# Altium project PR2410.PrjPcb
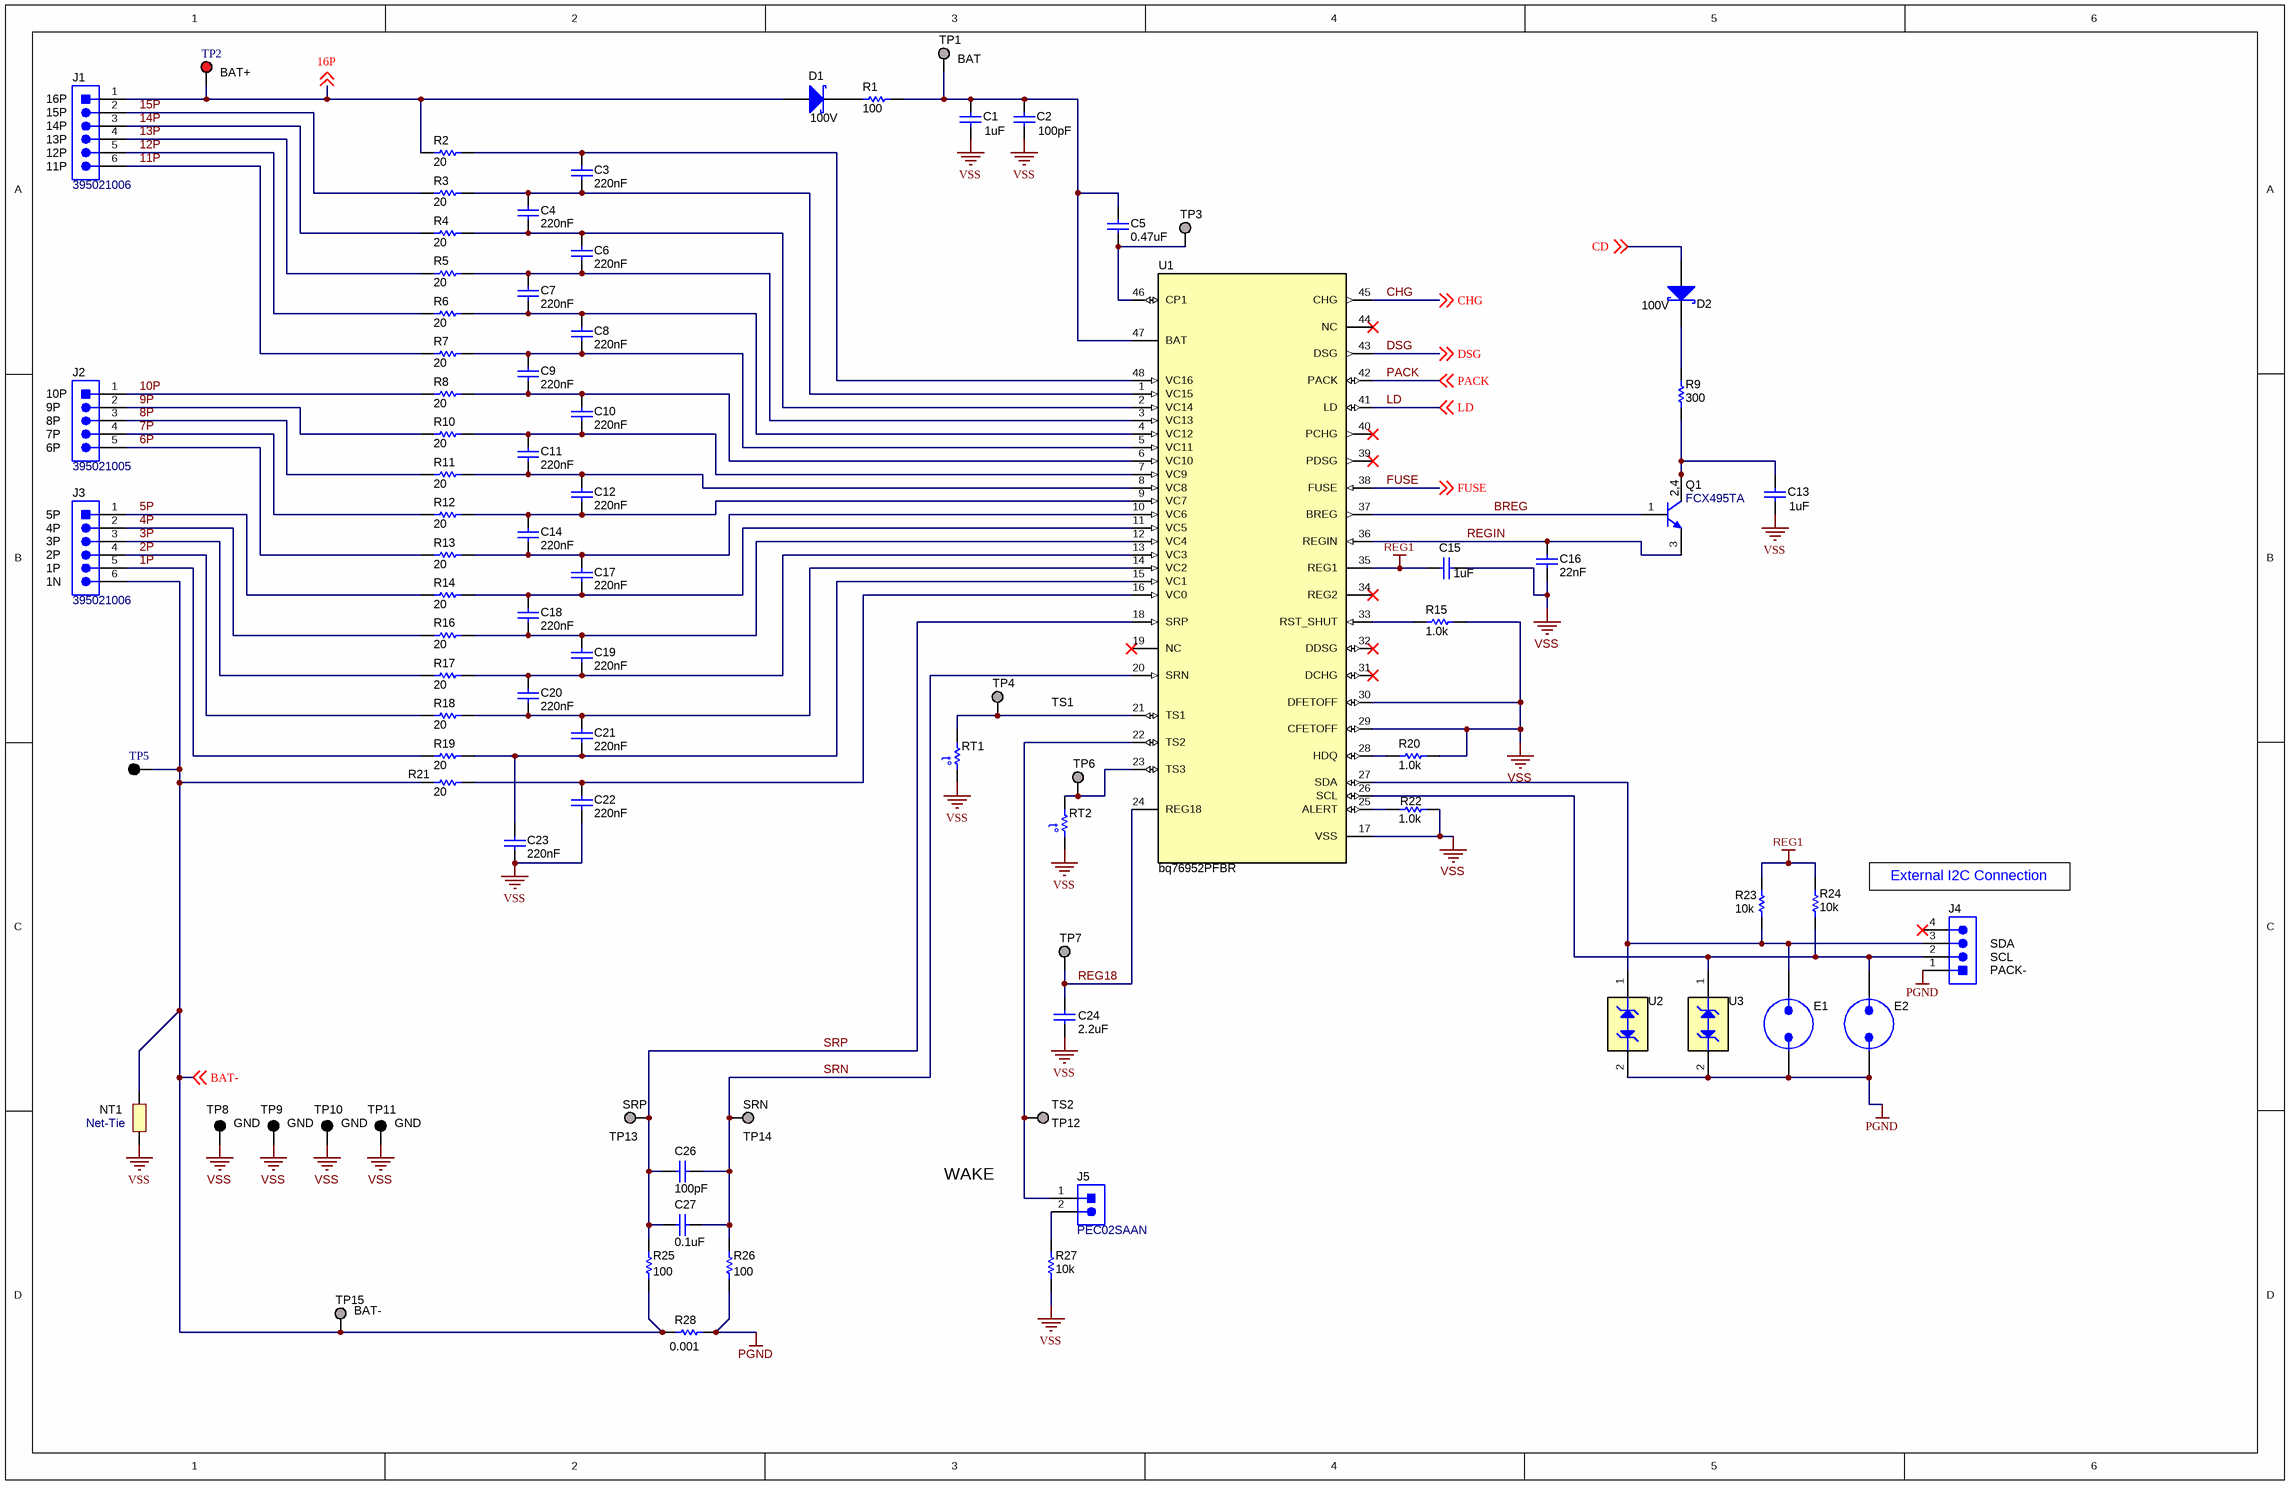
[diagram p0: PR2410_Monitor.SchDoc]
PCB_Rev: A; PRJ_Customer: Public Release; PRJ_Number: PR2410; PRJ_Title: BQ76952 2-layer test board; SCH_Rev: A; TID: N/A
3 sheets, 144 parts. Net scope: global (net labels, ports and power ports of the same name join across sheets).
Board file: PR2410.PcbDoc
Sheets:
  PR2410_Monitor.SchDoc
  PR2410_FETs.SchDoc
  PR2410_Hardware.SchDoc

## Sheet PR2410_Monitor.SchDoc: Monitor
size 431 x 279 mm; Date: Not shown in title block; ApprovedBy: Not shown in title block; CheckedBy: Not shown in title block; Author: Not shown in title block; CompanyName: Not shown in title block; Engineer: Not shown in title block; Organization: Not shown in title block; Address1: Not shown in title block; Address2: Not shown in title block; Address3: Not shown in title block; Address4: Not shown in title block; DocumentNumber: 1; Revision: Use project parameter SCH_Rev; SheetNumber: 1; SheetTotal: 3; PageSetup: Record=PageOptions¦CenterHorizontal=True¦CenterVertical=True¦PrintScale=1.00¦XCorrection=1.00¦YCorrection=1.00¦PrintKind=0¦BorderSize=5000000¦LeftOffset=0¦BottomOffset=0¦Orientation=2¦PaperLength=1000¦PaperWidth=1000¦Scale=100¦PaperSource=15¦PrintQuality=600¦MediaType=1¦DitherType=10¦PaperKind=Letter¦PrintScaleMode=1

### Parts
C1  ValueDisplayed: 1uF  [1206_180L]  (hidden comment: C3216X7R2A105K160AA)
C2  ValueDisplayed: 100pF  [0603]  (hidden comment: GCM1885C2A101JA16D)
C3  Cap_F: 220nF  [0603S]  (hidden comment: C1608X7R1H224K080AB)
C4  Cap_F: 220nF  [0603S]  (hidden comment: C1608X7R1H224K080AB)
C5  ValueDisplayed: 0.47uF  [0805_HV]  (hidden comment: GCM219R71E474KA55D)
C6  Cap_F: 220nF  [0603S]  (hidden comment: C1608X7R1H224K080AB)
C7  Cap_F: 220nF  [0603S]  (hidden comment: C1608X7R1H224K080AB)
C8  Cap_F: 220nF  [0603S]  (hidden comment: C1608X7R1H224K080AB)
C9  Cap_F: 220nF  [0603S]  (hidden comment: C1608X7R1H224K080AB)
C10  Cap_F: 220nF  [0603S]  (hidden comment: C1608X7R1H224K080AB)
C11  Cap_F: 220nF  [0603S]  (hidden comment: C1608X7R1H224K080AB)
C12  Cap_F: 220nF  [0603S]  (hidden comment: C1608X7R1H224K080AB)
C13  ValueDisplayed: 1uF  [1206_180]  (hidden comment: C3216X7R2A105K160AA)
C14  Cap_F: 220nF  [0603S]  (hidden comment: C1608X7R1H224K080AB)
C15  ValueDisplayed: 1uF  [0805_HV]  (hidden comment: EMK212B7105KG-T)
C16  Cap_F: 22nF  [0603]  (hidden comment: C0603C223K4RACTU)
C17  Cap_F: 220nF  [0603S]  (hidden comment: C1608X7R1H224K080AB)
C18  Cap_F: 220nF  [0603S]  (hidden comment: C1608X7R1H224K080AB)
C19  Cap_F: 220nF  [0603S]  (hidden comment: C1608X7R1H224K080AB)
C20  Cap_F: 220nF  [0603S]  (hidden comment: C1608X7R1H224K080AB)
C21  Cap_F: 220nF  [0603S]  (hidden comment: C1608X7R1H224K080AB)
C22  Cap_F: 220nF  [0603S]  (hidden comment: C1608X7R1H224K080AB)
C23  Cap_F: 220nF  [0603S]  (hidden comment: C1608X7R1H224K080AB)
C24  ValueDisplayed: 2.2uF  [0805_HV]  (hidden comment: EMK212B7225KG-T)
C26  ValueDisplayed: 100pF  [0603]  (hidden comment: GCM1885C2A101JA16D)
C27  ValueDisplayed: 0.1uF  [0603]  (hidden comment: 885012206095)
D1  value 100V  [SOD-123]  (hidden comment: BAT46W-7-F)
D2  value 100V  [SOD-123]  (hidden comment: BAT46W-7-F)
E1  Spark Gap  [SPARK_GAP2]  (value not drawn)  (no BOM)
E2  Spark Gap  [SPARK_GAP2]  (value not drawn)  (no BOM)
J1  395021006  [HEADER_395021006]
J2  395021005  [HEADER_395021005]
J3  395021006  [HEADER_395021006]
J4  22/05/3041  [CONN_22-05-3041]  (value not drawn)
J5  PEC02SAAN  [CONN_PEC02SAAN]
NT1  Net-Tie  [Net-Tie_10milWide_30milLong]  (net tie, no BOM)
Q1  FCX495TA  [SOT-89-3]
R1  ValueDisplayed: 100  [1210]  (hidden comment: CRCW1210100RFKEA)
R2  ValueDisplayed: 20  [1210]  (hidden comment: ERJ-14YJ200U)
R3  ValueDisplayed: 20  [1210]  (hidden comment: ERJ-14YJ200U)
R4  ValueDisplayed: 20  [1210]  (hidden comment: ERJ-14YJ200U)
R5  ValueDisplayed: 20  [1210]  (hidden comment: ERJ-14YJ200U)
R6  ValueDisplayed: 20  [1210]  (hidden comment: ERJ-14YJ200U)
R7  ValueDisplayed: 20  [1210]  (hidden comment: ERJ-14YJ200U)
R8  ValueDisplayed: 20  [1210]  (hidden comment: ERJ-14YJ200U)
R9  ValueDisplayed: 300  [2512]  (hidden comment: CRCW2512300RJNEG)
R10  ValueDisplayed: 20  [1210]  (hidden comment: ERJ-14YJ200U)
R11  ValueDisplayed: 20  [1210]  (hidden comment: ERJ-14YJ200U)
R12  ValueDisplayed: 20  [1210]  (hidden comment: ERJ-14YJ200U)
R13  ValueDisplayed: 20  [1210]  (hidden comment: ERJ-14YJ200U)
R14  ValueDisplayed: 20  [1210]  (hidden comment: ERJ-14YJ200U)
R15  ValueDisplayed: 1.0k  [0603]  (hidden comment: CRCW06031K00JNEA)
R16  ValueDisplayed: 20  [1210]  (hidden comment: ERJ-14YJ200U)
R17  ValueDisplayed: 20  [1210]  (hidden comment: ERJ-14YJ200U)
R18  ValueDisplayed: 20  [1210]  (hidden comment: ERJ-14YJ200U)
R19  ValueDisplayed: 20  [1210]  (hidden comment: ERJ-14YJ200U)
R20  ValueDisplayed: 1.0k  [0603]  (hidden comment: CRCW06031K00JNEA)
R21  ValueDisplayed: 20  [1210]  (hidden comment: ERJ-14YJ200U)
R22  ValueDisplayed: 1.0k  [0603]  (hidden comment: CRCW06031K00JNEA)
R23  ValueDisplayed: 10k  [0603]  (hidden comment: CRCW060310K0JNEA)
R24  ValueDisplayed: 10k  [0603]  (hidden comment: CRCW060310K0JNEA)
R25  ValueDisplayed: 100  [0603]  (hidden comment: Resistor)
R26  ValueDisplayed: 100  [0603]  (hidden comment: Resistor)
R27  ValueDisplayed: 10k  [0603]  (hidden comment: CRCW060310K0JNEA)
R28  ValueDisplayed: 0.001  [1210M]  (hidden comment: Resistor)
RT1  Thermistor  [THERMISTOR_103AT-2]  (value not drawn)
RT2  Thermistor  [THERMISTOR_103AT-2]  (value not drawn)
TP1  TESTPOINT  [TP_VIA_060RND040]  (value not drawn)  (no BOM)
TP2  TESTPOINT  [Keystone5010]  (value not drawn)
TP3  TESTPOINT  [TP_VIA_060RND040]  (value not drawn)  (no BOM)
TP4  TESTPOINT  [TP_VIA_060RND040]  (value not drawn)  (no BOM)
TP5  TESTPOINT  [Keystone5011]  (value not drawn)
TP6  TESTPOINT  [TP_VIA_060RND040]  (value not drawn)  (no BOM)
TP7  TESTPOINT  [TP_VIA_060RND040]  (value not drawn)  (no BOM)
TP8  5006  [Keystone5006]  (value not drawn)
TP9  5006  [Keystone5006]  (value not drawn)
TP10  5006  [Keystone5006]  (value not drawn)
TP11  5006  [Keystone5006]  (value not drawn)
TP12  TESTPOINT  [TP_VIA_060RND040]  (value not drawn)  (no BOM)
TP13  TESTPOINT  [TP_VIA_060RND040]  (value not drawn)  (no BOM)
TP14  TESTPOINT  [TP_VIA_060RND040]  (value not drawn)  (no BOM)
TP15  TESTPOINT  [TP_VIA_060RND040]  (value not drawn)  (no BOM)
U1  bq76952PFBR  [PFB0048A_N]
U2  TPD1E10B06DPYR  [DPY0002A]  (value not drawn)
U3  TPD1E10B06DPYR  [DPY0002A]  (value not drawn)

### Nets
PGND: E1.2 E2.2 J4.1 R26.1 R28.1 U2.2(A) U3.2(A)
REG1: C15.2 R23.1 R24.1 U1.35(REG1)
VSS: C1.2 C2.2 C13.2 C15.1 C16.1 C22.2 C23.2 C24.1 NT1.1 R15.1 R20.1 R22.1 R27.1 RT1.2 RT2.2 TP8.1 TP9.1 TP10.1 TP11.1 U1.17(VSS) U1.29(CFETOFF) U1.30(DFETOFF)
1P: J3.5 R19.1
2P: J3.4 R18.1
3P: J3.3 R17.1
4P: J3.2 R16.1
5P: J3.1 R14.1
6P: J2.5 R13.1
7P: J2.4 R12.1
8P: J2.3 R11.1
9P: J2.2 R10.1
10P: J2.1 R8.1
11P: J1.6 R7.1
12P: J1.5 R6.1
13P: J1.4 R5.1
14P: J1.3 R4.1
15P: J1.2 R3.1
16P: D1.2(A) J1.1 R2.1 TP2.1 ; off-sheet 16P
BAT-: J3.6 NT1.2 R21.1 R25.1 R28.2 TP5.1 TP15.1 ; off-sheet BAT-
BREG: Q1.1(B) U1.37(BREG)
CD: D2.2(A) ; off-sheet CD
CHG: U1.45(CHG) ; off-sheet CHG
DSG: U1.43(DSG) ; off-sheet DSG
FUSE: U1.38(FUSE) ; off-sheet FUSE
LD: U1.41(LD) ; off-sheet LD
PACK: U1.42(PACK) ; off-sheet PACK
REG18: C24.2 TP7.1 U1.24(REG18)
REGIN: C16.2 Q1.3(E) U1.36(REGIN)
SRN: C26.2 C27.2 R26.2 TP14.1 U1.20(SRN)
SRP: C26.1 C27.1 R25.2 TP13.1 U1.18(SRP)
NetC1_1: C1.1 C2.1 C5.1 R1.1 TP1.1 U1.47(BAT)
NetC3_1: C3.1 R2.2 U1.48(VC16)
NetC3_2: C3.2 C4.1 R3.2 U1.1(VC15)
NetC4_2: C4.2 C6.1 R4.2 U1.2(VC14)
NetC5_2: C5.2 TP3.1 U1.46(CP1)
NetC6_2: C6.2 C7.1 R5.2 U1.3(VC13)
NetC7_2: C7.2 C8.1 R6.2 U1.4(VC12)
NetC8_2: C8.2 C9.1 R7.2 U1.5(VC11)
NetC9_2: C9.2 C10.1 R8.2 U1.6(VC10)
NetC10_2: C10.2 C11.1 R10.2 U1.7(VC9)
NetC11_2: C11.2 C12.1 R11.2 U1.8(VC8)
NetC12_2: C12.2 C14.1 R12.2 U1.9(VC7)
NetC13_1: C13.1 Q1.2(C) Q1.4(C) R9.1
NetC14_2: C14.2 C17.1 R13.2 U1.10(VC6)
NetC17_2: C17.2 C18.1 R14.2 U1.11(VC5)
NetC18_2: C18.2 C19.1 R16.2 U1.12(VC4)
NetC19_2: C19.2 C20.1 R17.2 U1.13(VC3)
NetC20_2: C20.2 C21.1 R18.2 U1.14(VC2)
NetC21_2: C21.2 C23.1 R19.2 U1.15(VC1)
NetC22_1: C22.1 R21.2 U1.16(VC0)
NetD1_1: D1.1(K) R1.2
NetD2_1: D2.1(K) R9.2
NetE1_1: E1.1 J4.3 R23.2 U1.27(SDA) U2.1(K)
NetE2_1: E2.1 J4.2 R24.2 U1.26(SCL) U3.1(K)
NetJ5_1: J5.1 TP12.1 U1.22(TS2)
NetJ5_2: J5.2 R27.2
NetR15_2: R15.2 U1.33(RST_SHUT)
NetR20_2: R20.2 U1.28(HDQ)
NetR22_2: R22.2 U1.25(ALERT)
NetRT1_1: RT1.1 TP4.1 U1.21(TS1)
NetRT2_1: RT2.1 TP6.1 U1.23(TS3)

Not connected (* = marked no-connect by the designer): J4 4*; U1 19(NC)* 31(DCHG)* 32(DDSG)* 34(REG2)* 39(PDSG)* 40(PCHG)* 44(NC)*

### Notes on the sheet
- (near J1) 16P
- (near TP2) BAT+
- (near TP1) BAT
- (near J1) 12P
- (near J1) 11P
- (near J1) 14P
- (near J1) 13P
- (near J1) 15P
- (near J2) 7P
- (near J2) 8P
- (near J2) 9P
- (near J2) 10P
- (near J2) 6P
- (near J3) 2P
- (near J3) 1P
- (near J3) 4P
- (near J3) 3P
- (near J3) 5P
- (near J3) 1N
- TS1
- External I2C Connection
- (near J4) PACK-
- (near J4) SDA
- (near J4) SCL
- (near TP13) SRP
- (near TP14) SRN
- (near TP12) TS2
- GND
- (near TP11) GND
- WAKE
- (near TP15) BAT-

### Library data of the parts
C1 = CMP-0008710-2: CAP, CERM, 1 uF, 100 V, +/- 10%, X7R, 1206; Manufacturer: TDK; TaMin_C: -55°C; ESR_ohm: 4.575m; Polarized: N; SizeAreaWB_mm2: 10.92; Value1: 0.004575 ohm; U/M: EA; Value: 1uF; TaMax_C: 125°C; SizeZ_mm: 1.8; SizeX_mm: 3.2; SizeY_mm: 1.6; Cap_Case: 1206_180; Value2: 100V; SizeArea_mm2: 5.12; Cap_F: 1µF; IRMS_A: 3.39639A; AEC Category: Q200
C2 C26 = CMP-0007130-4: CAP, CERM, 100 pF, 100 V, +/- 5%, C0G/NP0, AEC-Q200 Grade 1, 0603; Manufacturer: MuRata; TaMin_C: -55°C; Polarized: N; SizeAreaWB_mm2: 4.68; Value1: Unknown; U/M: EA; TaMax_C: 125°C; SizeZ_mm: 1; SizeX_mm: 1.6; SizeY_mm: 0.8; Value2: 100V; SizeArea_mm2: 1.28; AEC Qualified: Y; AEC Category: Q200; Value: 100pF
C3 C4 C6-C8 = CMP-0007047-4: CAP, CERM, 0.22 uF, 50 V, +/- 10%, X7R, 0603; Manufacturer: TDK; TaMin_C: -55°C; Polarized: N; SizeAreaWB_mm2: 4.68; Value1: 0.021699 ohm; U/M: EA; Value: 0.22uF; TaMax_C: 125°C; SizeZ_mm: 1; SizeX_mm: 1.6; SizeY_mm: 0.8; Cap_Case: 0603; Value2: 50V; SizeArea_mm2: 1.28; AEC Category: Q200; ESR_ohm: 0.021699; IRMS_A: 1.12496A
C5 = CMP-0008010-2: CAP, CERM, 0.47 uF, 25 V, +/- 10%, X7R, AEC-Q200 Grade 1, 0805; Manufacturer: MuRata; TaMin_C: -55°C; Polarized: N; SizeAreaWB_mm2: 6.75; Value1: Unknown; U/M: EA; Value: 0.47uF; TaMax_C: 125°C; SizeZ_mm: 1.45; SizeX_mm: 2; SizeY_mm: 1.25; Cap_Case: 0805; Value2: 25V; SizeArea_mm2: 2.5; AEC Qualified: Y; Cap_F: 470nF; AEC Grade: 1; AEC Category: Q200
C9-C12 C14 C17-C19 C21-C23 = CMP-0007047-4: CAP, CERM, 0.22 uF, 50 V, +/- 10%, X7R, 0603; Manufacturer: TDK; TaMin_C: -55°C; ESR_ohm: 0.021699; Polarized: N; SizeAreaWB_mm2: 4.68; Value1: 0.021699 ohm; U/M: EA; Value: 0.22uF; TaMax_C: 125°C; SizeZ_mm: 1; SizeX_mm: 1.6; SizeY_mm: 0.8; Cap_Case: 0603; Value2: 50V; SizeArea_mm2: 1.28; IRMS_A: 1.12496A; AEC Category: Q200
C13 = CMP-0008710-2: CAP, CERM, 1 uF, 100 V, +/- 10%, X7R, 1206; Manufacturer: TDK; TaMin_C: -55°C; ESR_ohm: 4.575m; Polarized: N; SizeAreaWB_mm2: 10.92; Value1: 0.004575 ohm; U/M: EA; Value: 1uF; TaMax_C: 125°C; SizeZ_mm: 1.8; SizeX_mm: 3.2; SizeY_mm: 1.6; Value2: 100V; SizeArea_mm2: 5.12; Cap_F: 1µF; IRMS_A: 3.39639A; AEC Category: Q200
C15 = CMP-0008000-2: CAP, CERM, 1 uF, 16 V, +/- 10%, X7R, 0805; Manufacturer: Taiyo Yuden; TaMin_C: -55°C; Polarized: N; SizeAreaWB_mm2: 6.75; Value1: Unknown; U/M: EA; Value: 1uF; TaMax_C: 125°C; SizeZ_mm: 1.45; SizeX_mm: 2; SizeY_mm: 1.25; Cap_Case: 0805; Value2: 16V; SizeArea_mm2: 2.5; Cap_F: 1µF; AEC Category: Q200
C16 = CMP-0006900-4: CAP, CERM, 0.022 uF, 16 V, +/- 10%, X7R, 0603; Manufacturer: Kemet; TaMin_C: -55°C; Polarized: N; SizeAreaWB_mm2: 4.68; Value1: Unknown; U/M: EA; TaMax_C: 125°C; SizeZ_mm: 1; SizeX_mm: 1.6; SizeY_mm: 0.8; Value2: 16V; SizeArea_mm2: 1.28; AEC Category: Q200
C20 = CMP-0007047-4: CAP, CERM, 0.22 uF, 50 V, +/- 10%, X7R, 0603; Manufacturer: TDK; TaMin_C: -55°C; ESR_ohm: 0.021699; Polarized: N; SizeAreaWB_mm2: 4.68; Value1: 0.021699 ohm; U/M: EA; Value: 0.22uF; TaMax_C: 125°C; SizeZ_mm: 1; SizeX_mm: 1.6; SizeY_mm: 0.8; Cap_Case: 0603; Value2: 50V; SizeArea_mm2: 1.28; CompType: Capacitor; IRMS_A: 1.12496A; AEC Category: Q200
C24 = CMP-0008001-2: CAP, CERM, 2.2 uF, 16 V, +/- 10%, X7R, 0805; Manufacturer: Taiyo Yuden; TaMin_C: -55°C; Polarized: N; SizeAreaWB_mm2: 6.75; Value1: Unknown; U/M: EA; Value: 2.2uF; TaMax_C: 125°C; SizeZ_mm: 1.45; SizeX_mm: 2; SizeY_mm: 1.25; Cap_Case: 0805; Value2: 16V; SizeArea_mm2: 2.5; Cap_F: 2.2µF; AEC Category: Q200
C27 = CMP-0006837-4: CAP, CERM, 0.1 uF, 50 V, +/- 10%, X7R, 0603; Manufacturer: Wurth Elektronik; TaMin_C: -55°C; Polarized: N; SizeAreaWB_mm2: 4.68; Value1: Unknown; U/M: EA; Value: 0.1uF; TaMax_C: 125°C; SizeZ_mm: 1; SizeX_mm: 1.6; SizeY_mm: 0.8; Value2: 50V; SizeArea_mm2: 1.28; Cap_F: 100nF; AEC Category: Q200
D1 D2 = CMP-0028450-2: Diode, Schottky, 100 V, 0.15 A, SOD-123; Manufacturer: Diodes Inc.; Io_A: 150mA; SizeArea_mm2: 6.545; SizeX_mm: 3.85; Value2: 0.6V; Value1: 0.15A; AEC Category: Q101; SizeZ_mm: 1.35; SizeY_mm: 1.7; Green_Lifecycle: Active; Green_REACh: Passed; SizeAreaWB_mm2: 13.095; Vf_V: 600mV
E1 E2 = CMP-0079939-1
J1 J3 = CMP-0055336-1: Terminal Block Header, 3.5mm 6x1, Tin, R/A, TH; Manufacturer: Molex; CNHeader: FALSE; CT: TRUE; Green_Lifecycle: Active; Green_REACh: Passed
J2 = CMP-0055189-1: Header (shrouded), 3.5mm, 5x1, R/A, TH; Manufacturer: Molex; CNHeader: FALSE; Green_Lifecycle: Active; Green_REACh: Passed
J4 = CMP-0055187-1: Header (friction lock), 100mil, 4x1, R/A, TH; Manufacturer: Molex; PartNumber: 0022053041; Green_Lifecycle: Active; Green_REACh: Passed; CNHeader: FALSE
J5 = CMP-0002337-1: Header, 100mil, 2x1, Tin, TH; Manufacturer: Sullins Connector Solutions; CNHeader: TRUE; Current_A: 3A; Green_Lifecycle: Not Set; Shrouded: N; Gender: Male; Green_REACh: Incomplete; Voltage_V: 1.8kV; Row_Count: 1; Pitch_mm: 2.54; CT: FALSE; Cert_UL: Y
NT1 = CMP-0078142-3: Single point connection between nets.
Q1 = CMP-0000510-2: Transistor, NPN, 150 V, 1 A, AEC-Q101, SOT-89; Manufacturer: Diodes Inc.; TaMax_C: 150°C; Value2: 300; Value1: 1 A; Vcesat1_V: 200mV; SizeX_mm: 4.1; SizeY_mm: 4.5; TaMin_C: -65°C; IcRated_A: 1A; CompType: BJT; SizeZ_mm: 1.5; AEC Qualified: Y; Value: 150 V; SizeArea_mm2: 18.45; NPN: 1; Vceo_V: 150V; PNP: 0; AEC Category: Q101; SizeAreaWB_mm2: 28.05; U/M: EA
R1 = CMP-0082536-1: RES, 100, 1%, 0.5 W, AEC-Q200 Grade 0, 1210; Manufacturer: Vishay-Dale; Value: 100; Value_Code: 100R; Power_W: 500mW; Value2: 0.5W; VDC_V: 200V; TempCo: 100 ppm/C; EIA_Code: E96; SizeArea_mm2: 8; SizeX_mm: 3.2; SizeY_mm: 2.5; SizeZ_mm: 1.35; AEC Category: Q200; AEC Qualified: Y; AEC Grade: 0; SizeAreaWB_mm2: 14.7
R2-R7 R10-R12 R14 R16 R17 R19 R21 = CMP-0015332-2: RES, 20, 5%, 0.5 W, 1210; Manufacturer: Panasonic; Value: 20; Value_Code: 20R0; Power_W: 500mW; Value2: 0.5W; VDC_V: 200V; TempCo: 200 ppm/C; EIA_Code: E24; SizeArea_mm2: 8; SizeX_mm: 3.2; SizeY_mm: 2.5; SizeZ_mm: 1.35; AEC Category: Q200; SizeAreaWB_mm2: 14.7; U/M: EA
R8 R13 R18 = CMP-0015332-2: RES, 20, 5%, 0.5 W, 1210; Manufacturer: Panasonic; CompType: Resistor; Value: 20; Value_Code: 20R0; Power_W: 500mW; Value2: 0.5W; VDC_V: 200V; TempCo: 200 ppm/C; EIA_Code: E24; SizeArea_mm2: 8; SizeX_mm: 3.2; SizeY_mm: 2.5; SizeZ_mm: 1.35; AEC Category: Q200; SizeAreaWB_mm2: 14.7; U/M: EA
R9 = CMP-0015938-3: RES, 300, 5%, 1 W, AEC-Q200 Grade 0, 2512; Manufacturer: Vishay-Dale; Power_W: 1W; TempCo: 200 ppm/C; Value_Code: 300R; Value: 300; EIA_Code: E24; SizeX_mm: 6.3; SizeY_mm: 3.2; SizeZ_mm: 0.71; SizeArea_mm2: 20.16; AEC Qualified: Y; VDC_V: 500V; AEC Grade: 0; AEC Category: Q200
R15 R20 R22 = CMP-0025729-4: RES, 1.0 k, 5%, 0.1 W, AEC-Q200 Grade 0, 0603; Manufacturer: Vishay-Dale; Power_W: 100mW; TempCo: 200 ppm/C; Value_Code: 1k00; Value: 1.0k; EIA_Code: E24; Res_ohm: 1k; SizeX_mm: 1.6; SizeY_mm: 0.8; SizeZ_mm: 1; Value2: 0.1W; SizeArea_mm2: 1.28; AEC Qualified: Y; VDC_V: 75V; AEC Category: Q200; AEC Grade: 0
R23 = CMP-0025701-4: RES, 10 k, 5%, 0.1 W, AEC-Q200 Grade 0, 0603; Manufacturer: Vishay-Dale; Power_W: 100mW; TempCo: 200 ppm/C; Value_Code: 10k0; Value: 10k; EIA_Code: E24; SizeX_mm: 1.6; SizeY_mm: 0.8; SizeZ_mm: 1; Value2: 0.1W; SizeArea_mm2: 1.28; AEC Qualified: Y; VDC_V: 75V; AEC Category: Q200; AEC Grade: 0
R24 = CMP-0025701-4: RES, 10 k, 5%, 0.1 W, AEC-Q200 Grade 0, 0603; Manufacturer: Vishay-Dale; Power_W: 100mW; TempCo: 200 ppm/C; Value_Code: 10k0; Value: 10k; EIA_Code: E24; SizeX_mm: 1.6; SizeY_mm: 0.8; SizeZ_mm: 1; Value2: 0.1W; SizeArea_mm2: 1.28; CompType: Resistor; AEC Qualified: Y; VDC_V: 75V; AEC Category: Q200; AEC Grade: 0
R25 R26 = CMP-0025700-4: RES, 100, 5%, 0.1 W, AEC-Q200 Grade 0, 0603; PartNumber: CRCW0603100RJNEA; Manufacturer: Vishay-Dale; Value: 100; Value_Code: 100R; Power_W: 100mW; Value2: 0.1W; VDC_V: 75V; TempCo: 200 ppm/C; EIA_Code: E24; U/M: EA; SizeArea_mm2: 1.28; SizeX_mm: 1.6; SizeY_mm: 0.8; SizeZ_mm: 1; AEC Category: Q200; AEC Qualified: Y; AEC Grade: 0
R27 = CMP-0025701-4: RES, 10 k, 5%, 0.1 W, AEC-Q200 Grade 0, 0603; Manufacturer: Vishay-Dale; Power_W: 100mW; TempCo: 200 ppm/C; Value_Code: 10k0; Value: 10k; EIA_Code: E24; SizeX_mm: 1.6; SizeY_mm: 0.8; SizeZ_mm: 1; Value2: 0.1W; SizeArea_mm2: 1.28; AEC Qualified: Y; VDC_V: 75V; AEC Grade: 0; AEC Category: Q200
R28 = CMP-0015200-2: RES, 0.001, 1%, 1 W, 1210; PartNumber: PMR25HZPFV1L00; Manufacturer: Rohm; Value: 0.001; Res_ohm: 1m; Value_Code: 1L000; Power_W: 1W; TempCo: 100 ppm/C; EIA_Code: E96; U/M: EA; SizeArea_mm2: 8; SizeAreaWB_mm2: 14.7; SizeX_mm: 3.2; SizeY_mm: 2.5; SizeZ_mm: 1.35; AEC Category: Q200; Green_Lifecycle: Active; Green_REACh: Passed
RT1 RT2 = CMP-0002341-2: Thermistor NTC, 10.0k ohm, 1%, Disc, 5x8.4 mm; PartNumber: 103AT-2; Manufacturer: SEMITEC Corporation; Power_W: 10mW; TaMin_C: -50°C; TaMax_C: 110°C; U/M: EA; Value: 10k
TP1 TP3 TP4 TP6 TP7 TP12-TP15 = CMP-0078143-3: TEST POINT.  No entry in BOM.
TP2 = CMP-0055147-1: Test Point, Multipurpose, Red, TH; Manufacturer: Keystone; CNHeader: FALSE; Green_Lifecycle: Active; Green_REACh: Passed; ContactFinish: Silver; CT: TRUE
TP5 = CMP-0055148-1: Test Point, Multipurpose, Black, TH; Manufacturer: Keystone; CNHeader: FALSE; Green_Lifecycle: Active; Green_REACh: Passed; ContactFinish: Silver; CT: TRUE
TP8-TP11 = CMP-0055143-1: Test Point, Compact, Black, TH; Manufacturer: Keystone; ContactFinish: Silver; Green_Lifecycle: Active; Green_REACh: Passed; CNHeader: FALSE; CT: TRUE
U1 = CMP-0084230-1: Multicell Battery Monitor and Protection Family, PFB0048A (TQFP-48); Alternate PartNumber: bq76952PFBT; Alternate Manufacturer: Texas Instruments; SizeZ_mm: 1.2; SizeX_mm: 9; AEC Qualified: N; CompType: IC; SizeAreaWB_mm2: 121; SizeArea_mm2: 81; AEC Category: Q200
U2 U3 = CMP-0043093-4: Single-Channel ESD in 0402 Package With 10pF Capacitance and 6V Breakdown, DPY0002A (X1SON-2); Manufacturer: Texas Instruments; Alternate PartNumber: TPD1E10B06DPYT; IEC 61000-4-2 Air-Gap(+/- kV): 30; Eco-Plan: TBD; IO Capacitance(Typ)(pF): 10; Breakdown Voltage(Min)(V): 6; AEC Category: Q200; AEC Qualified: N; CompType: IC; Green_Lifecycle: Active; Green_REACh: Passed; SizeAreaWB_mm2: 3.2; SizeArea_mm2: 0.6; SizeX_mm: 1.0; SizeZ_mm: 0.45; Rating: Catalog

## Sheet PR2410_FETs.SchDoc: FETs
size 431 x 279 mm; Date: Not shown in title block; ApprovedBy: Not shown in title block; CheckedBy: Not shown in title block; Author: Not shown in title block; CompanyName: Not shown in title block; DrawnBy: M Sunna; Engineer: Not shown in title block; Organization: Not shown in title block; Address1: Not shown in title block; Address2: Not shown in title block; Address3: Not shown in title block; Address4: Not shown in title block; DocumentNumber: 2; Revision: Use project parameter SCH_Rev; SheetNumber: 2; SheetTotal: 3; PageSetup: Record=PageOptions¦CenterHorizontal=True¦CenterVertical=True¦PrintScale=1.00¦XCorrection=1.00¦YCorrection=1.00¦PrintKind=0¦BorderSize=5000000¦LeftOffset=0¦BottomOffset=0¦Orientation=2¦PaperLength=1000¦PaperWidth=1000¦Scale=100¦PaperSource=15¦PrintQuality=600¦MediaType=1¦DitherType=10¦PaperKind=Letter¦PrintScaleMode=1
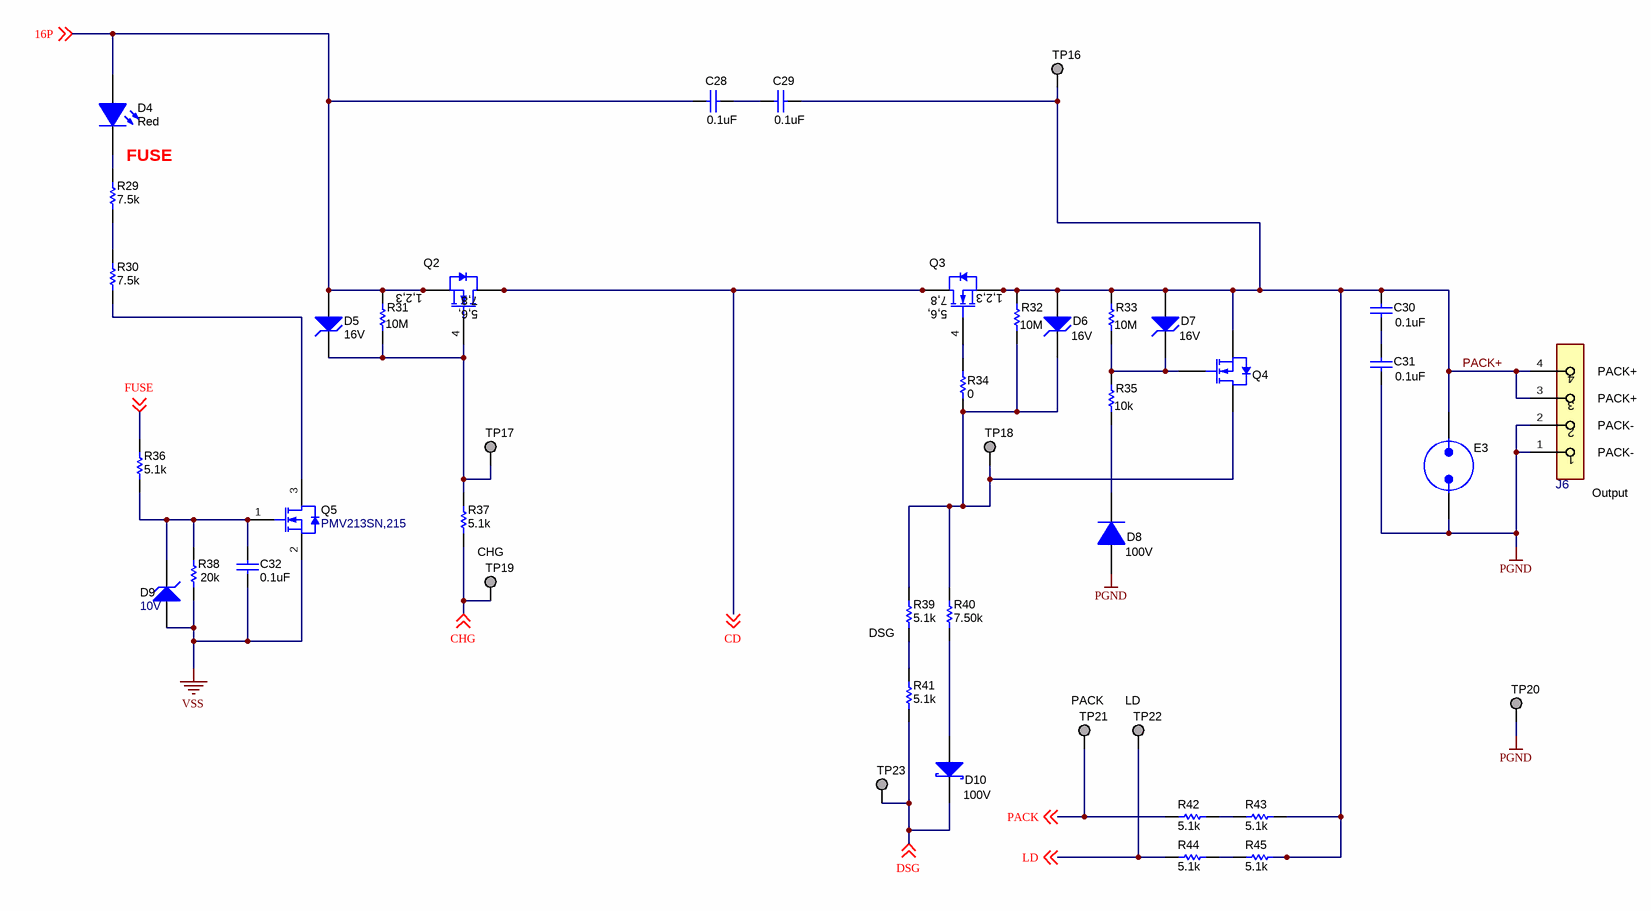
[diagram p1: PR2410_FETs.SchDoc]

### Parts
C28  ValueDisplayed: 0.1uF  [0603]  (hidden comment: GCJ188R72A104KA01D)
C29  ValueDisplayed: 0.1uF  [0603]  (hidden comment: GCJ188R72A104KA01D)
C30  ValueDisplayed: 0.1uF  [0603]  (hidden comment: GCJ188R72A104KA01D)
C31  ValueDisplayed: 0.1uF  [0603]  (hidden comment: GCJ188R72A104KA01D)
C32  ValueDisplayed: 0.1uF  [0603]  (hidden comment: 885012206095)
D4  value Red  [WL-SMCW_RED]  (hidden comment: 150060RS75000)
D5  value 16V  [SOD-123]  (hidden comment: MMSZ5246B-7-F)
D6  value 16V  [SOD-123]  (hidden comment: MMSZ5246B-7-F)
D7  value 16V  [SOD-123]  (hidden comment: MMSZ5246B-7-F)
D8  value 100V  [SOD-123]  (hidden comment: 1N4148W-7-F)
D9  value 10V  [SOD-123]  (hidden comment: MMSZ4697T1G)
D10  Vr_V: 100V  [SOD-123]  (hidden comment: BAT46W-7-F)
E3  Spark Gap  [SPARK_GAP2]  (value not drawn)  (no BOM)
J6  OSTTE040161  [FP-OSTTE040161_HDR4-MFG]  (value not drawn)
Q2  BSC160N15NS5ATMA1  [PG-TDSON-8]  (value not drawn)
Q3  BSC160N15NS5ATMA1  [PG-TDSON-8]  (value not drawn)
Q4  MOSFET_N_D3G1S2  [SOT-323]  (value not drawn)
Q5  PMV213SN,215  [SOT-23]
R29  ValueDisplayed: 7.5k  [1206]  (hidden comment: CRCW12067K50JNEA)
R30  ValueDisplayed: 7.5k  [1206]  (hidden comment: CRCW12067K50JNEA)
R31  ValueDisplayed: 10M  [0603]  (hidden comment: Resistor)
R32  ValueDisplayed: 10M  [0603]  (hidden comment: Resistor)
R33  ValueDisplayed: 10M  [0603]  (hidden comment: Resistor)
R34  ValueDisplayed: 0  [0603]  (hidden comment: CRCW06030000Z0EA)
R35  ValueDisplayed: 10k  [0603]  (hidden comment: Resistor)
R36  ValueDisplayed: 5.1k  [0603]  (hidden comment: Resistor)
R37  ValueDisplayed: 5.1k  [0603]  (hidden comment: CRCW06035K10JNEA)
R38  ValueDisplayed: 20k  [0603]  (hidden comment: Resistor)
R39  ValueDisplayed: 5.1k  [1206]  (hidden comment: CRCW12065K10JNEA)
R40  ValueDisplayed: 7.50k  [0603]  (hidden comment: CRCW06037K50FKEA)
R41  ValueDisplayed: 5.1k  [1206]  (hidden comment: CRCW12065K10JNEA)
R42  ValueDisplayed: 5.1k  [1206]  (hidden comment: CRCW12065K10JNEA)
R43  ValueDisplayed: 5.1k  [1206]  (hidden comment: CRCW12065K10JNEA)
R44  ValueDisplayed: 5.1k  [1206]  (hidden comment: CRCW12065K10JNEA)
R45  ValueDisplayed: 5.1k  [1206]  (hidden comment: CRCW12065K10JNEA)
TP16  TESTPOINT  [TP_VIA_060RND040]  (value not drawn)  (no BOM)
TP17  TESTPOINT  [TP_VIA_060RND040]  (value not drawn)  (no BOM)
TP18  TESTPOINT  [TP_VIA_060RND040]  (value not drawn)  (no BOM)
TP19  TESTPOINT  [TP_VIA_060RND040]  (value not drawn)  (no BOM)
TP20  TESTPOINT  [TP_VIA_060RND040]  (value not drawn)  (no BOM)
TP21  TESTPOINT  [TP_VIA_060RND040]  (value not drawn)  (no BOM)
TP22  TESTPOINT  [TP_VIA_060RND040]  (value not drawn)  (no BOM)
TP23  TESTPOINT  [TP_VIA_060RND040]  (value not drawn)  (no BOM)

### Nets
PGND: C31.1 D8.2(A) E3.2 J6.1 J6.2 TP20.1
VSS: C32.1 D9.2(A) Q5.2(S) R38.1
16P: C28.2 D4.2(A) D5.2(A) Q2.1(S) Q2.2(S) Q2.3(S) R31.1 ; off-sheet 16P
CD: Q2.5(D) Q2.6(D) Q2.7(D) Q2.8(D) Q2.9(D) Q3.5(D) Q3.6(D) Q3.7(D) Q3.8(D) Q3.9(D) ; off-sheet CD
CHG: R37.1 TP19.1 ; off-sheet CHG
DSG: D10.1(K) R41.1 TP23.1 ; off-sheet DSG
FUSE: R36.2 ; off-sheet FUSE
LD: R44.2 TP22.1 ; off-sheet LD
PACK: R42.2 TP21.1 ; off-sheet PACK
PACK+: C29.1 C30.2 D6.2(A) D7.2(A) E3.1 J6.3 J6.4 Q3.1(S) Q3.2(S) Q3.3(S) Q4.2(S) R32.1 R33.1 R43.1 R45.1 TP16.1
NetC28_1: C28.1 C29.2
NetC30_1: C30.1 C31.2
NetC32_2: C32.2 D9.1(K) Q5.1(G) R36.1 R38.2
NetD4_1: D4.1(K) R29.2
NetD5_1: D5.1(K) Q2.4(G) R31.2 R37.2 TP17.1
NetD6_1: D6.1(K) Q4.3(D) R32.2 R34.2 R39.2 R40.2 TP18.1
NetD7_1: D7.1(K) Q4.1(G) R33.2 R35.1
NetD8_1: D8.1(K) R35.2
NetD10_2: D10.2(A) R40.1
NetQ3_4: Q3.4(G) R34.1
NetQ5_3: Q5.3(D) R30.1
NetR29_1: R29.1 R30.2
NetR39_1: R39.1 R41.2
NetR42_1: R42.1 R43.2
NetR44_1: R44.1 R45.2

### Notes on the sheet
- FUSE
- (near J6) PACK+
- (near J6) PACK-
- (near J6) Output
- CHG
- (near R39) DSG
- (near TP21) PACK
- (near TP22) LD

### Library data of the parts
C28 C29 = CMP-0064935-4: CAP, CERM, 0.1 uF, 100 V,+/- 10%, X7R, AEC-Q200 Grade 1, 0603; Manufacturer: MuRata; TaMin_C: -55°C; Polarized: N; SizeAreaWB_mm2: 4.68; Value1: Unknown; U/M: EA; Value: 0.1uF; TaMax_C: 125°C; SizeZ_mm: 1; SizeX_mm: 1.6; SizeY_mm: 0.8; Value2: 100V; SizeArea_mm2: 1.28; AEC Qualified: Y; Cap_F: 100nF; AEC Category: Q200
C30 C31 = CMP-0064935-4: CAP, CERM, 0.1 uF, 100 V,+/- 10%, X7R, AEC-Q200 Grade 1, 0603; Manufacturer: MuRata; Polarized: N; Value: 0.1uF; U/M: EA; Cap_F: 100nF; Value1: Unknown; VDC_V: 100V; TaMin_C: -55°C; TaMax_C: 125°C; SizeArea_mm2: 1.28; SizeAreaWB_mm2: 4.68; SizeX_mm: 1.6; SizeY_mm: 0.8; SizeZ_mm: 1; AEC Category: Q200; AEC Qualified: Y
C32 = CMP-0006837-4: CAP, CERM, 0.1 uF, 50 V, +/- 10%, X7R, 0603; Manufacturer: Wurth Elektronik; Polarized: N; Value: 0.1uF; U/M: EA; Cap_F: 100nF; Value1: Unknown; VDC_V: 50V; TaMin_C: -55°C; TaMax_C: 125°C; SizeArea_mm2: 1.28; SizeAreaWB_mm2: 4.68; SizeX_mm: 1.6; SizeY_mm: 0.8; SizeZ_mm: 1; AEC Category: Q200
D4 = CMP-0002947-3: LED, Red, SMD; Manufacturer: Wurth Elektronik; Type: AlInGaP; Vf_V: 2V; Io_A: 30mA; Vr_V: 5V; Tjmax_C: 85°C; Power_TotalModule: 72mW; Value1: 0.072W; Angle: 140
D5 = CMP-0005754-4: Diode, Zener, 16 V, 500 mW, SOD-123; Manufacturer: Diodes Inc.; Power_W: 500mW; SizeAreaWB_mm2: 13.095; Value1: 0.5W; RJA_CperW: 350; SizeZ_mm: 1.35; SizeX_mm: 3.85; SizeY_mm: 1.7; SizeArea_mm2: 6.545; AEC Category: Q101
D6 D7 = CMP-0005754-4: Diode, Zener, 16 V, 500 mW, SOD-123; Manufacturer: Diodes Inc.; Power_W: 500mW; SizeY_mm: 1.7; Value1: 0.5W; SizeX_mm: 3.85; RJA_CperW: 350; SizeAreaWB_mm2: 13.095; SizeArea_mm2: 6.545; AEC Category: Q101; SizeZ_mm: 1.35
D8 = CMP-0029001-2: Diode, Ultrafast, 100 V, 0.15 A, SOD-123; Manufacturer: Diodes Inc.; Vf_V: 1.25V; Value1: 0.15A; Io_A: 1.5dA; TJmax_C: 150°C; SizeAreaWB_mm2: 13.095; SizeArea_mm2: 6.545; SizeX_mm: 3.85; SizeY_mm: 1.7; SizeZ_mm: 1.35; AEC Category: Q101; Green_Lifecycle: Active; Green_REACh: Passed
D9 = CMP-0005740-3: Diode, Zener, 10 V, 500 mW, SOD-123; Manufacturer: ON Semiconductor; SizeY_mm: 1.7; SizeX_mm: 3.85; RJA_CperW: 340; SizeAreaWB_mm2: 13.095; AEC Category: Q101; Power_W: 500mW; SizeZ_mm: 1.35; Value1: 0.5W; SizeArea_mm2: 6.545
D10 = CMP-0028450-2: Diode, Schottky, 100 V, 0.15 A, SOD-123; Manufacturer: Diodes Inc.; Value: 100V; Io_A: 150mA; SizeArea_mm2: 6.545; SizeX_mm: 3.85; Value2: 0.6V; Value1: 0.15A; AEC Category: Q101; SizeZ_mm: 1.35; SizeY_mm: 1.7; Green_Lifecycle: Active; Green_REACh: Passed; SizeAreaWB_mm2: 13.095; Vf_V: 600mV
E3 = CMP-0079939-1
J6 = CMP-0087048-1: TERM BLOCK 3.5MM VERT 4POS PCB; Manufacturer: On Shore Technology; Row_Count: 1; Current_A: 10A; ContactFinish: Tin; Voltage_V: 300V
Q2 Q3 = CMP-0067566-1: MOSFET, N-CH, 150 V, 56 A, PG-TDSON-8; Alternate Manufacturer: None; Manufacturer: Infineon Technologies; SizeZ_mm: 1.12; ChType: N; Value2: 19 nC; VdsMax_V: 150V; SizeX_mm: 5.99; SizeY_mm: 4.9; Vgs_V: 20V; QgTyp_nC: 19.0; Value: 150V; SizeArea_mm2: 29.351; AEC Category: Q101; IdsMax_A: 56A; SizeAreaWB_mm2: 55.131; U/M: EA; Value1: ? ohm
Q4 = CMP-0000774-1: MOSFET, N-CH, 60 V, 0.31 A, SOT-323; PartNumber: 2N7002KW; Manufacturer: Fairchild Semiconductor; Alternate Manufacturer: None; Value: 60V; U/M: EA; ChType: N; Value1: 1; Rdson45_ohm: 1.6; Vgs_V: 2.1V; IdsMax_A: 3.1dA; SizeAreaWB_mm2: 10.24; SizeArea_mm2: 4.84; SizeX_mm: 2.2; SizeZ_mm: 1.1; AEC Category: Q101; Green_Lifecycle: Active; Green_REACh: Passed
Q5 = CMP-0001015-3: MOSFET, N-CH, 100 V, 1.9 A, SOT-23; Alternate Manufacturer: None; Manufacturer: Nexperia; SizeZ_mm: 1.1; ChType: N; Value2: 7 nC; VdsMax_V: 100V; SizeX_mm: 2.5; SizeY_mm: 3; Vgs_V: 30V; QgTyp_nC: 7; Value: 100V; SizeArea_mm2: 7.5; AEC Category: Q101; IdsMax_A: 1.9A; SizeAreaWB_mm2: 14
R29 R30 = CMP-0018728-3: RES, 7.5 k, 5%, 0.25 W, AEC-Q200 Grade 0, 1206; Manufacturer: Vishay-Dale; Power_W: 250mW; TempCo: 200 ppm/C; Value_Code: 7k50; Value: 7.5k; EIA_Code: E24; SizeX_mm: 3.2; SizeY_mm: 1.6; SizeZ_mm: 1.35; Value2: 0.25W; SizeArea_mm2: 5.12; AEC Qualified: Y; VDC_V: 200V; AEC Category: Q200; AEC Grade: 0
R31-R33 = CMP-0025702-4: RES, 10 M, 5%, 0.1 W, AEC-Q200 Grade 0, 0603; PartNumber: CRCW060310M0JNEA; Manufacturer: Vishay-Dale; Value: 10Meg; Value_Code: 10M0; Power_W: 100mW; Value2: 0.1W; VDC_V: 75V; TempCo: 200 ppm/C; EIA_Code: E24; U/M: EA; SizeArea_mm2: 1.28; SizeX_mm: 1.6; SizeY_mm: 0.8; SizeZ_mm: 1; AEC Category: Q200; AEC Qualified: Y; AEC Grade: 0
R34 = CMP-0025697-4: RES, 0, 5%, 0.1 W, AEC-Q200 Grade 0, 0603; Manufacturer: Vishay-Dale; Value: 0; Value_Code: 0000; Power_W: 100mW; Value2: 0.1W; VDC_V: 75V; TempCo: 200 ppm/C; EIA_Code: E24; SizeArea_mm2: 1.28; SizeX_mm: 1.6; SizeY_mm: 0.8; SizeZ_mm: 1; AEC Category: Q200; AEC Qualified: Y
R35 = CMP-0025701-4: RES, 10 k, 5%, 0.1 W, AEC-Q200 Grade 0, 0603; PartNumber: CRCW060310K0JNEA; Manufacturer: Vishay-Dale; Value: 10k; Value_Code: 10k0; Power_W: 100mW; Value2: 0.1W; VDC_V: 75V; TempCo: 200 ppm/C; EIA_Code: E24; U/M: EA; SizeArea_mm2: 1.28; SizeX_mm: 1.6; SizeY_mm: 0.8; SizeZ_mm: 1; AEC Category: Q200; AEC Qualified: Y; AEC Grade: 0
R36 = CMP-0025830-4: RES, 5.1 k, 5%, 0.1 W, AEC-Q200 Grade 0, 0603; PartNumber: CRCW06035K10JNEA; Manufacturer: Vishay-Dale; Value: 5.1k; Value_Code: 5k10; Power_W: 100mW; Value2: 0.1W; VDC_V: 75V; TempCo: 200 ppm/C; EIA_Code: E24; U/M: EA; SizeArea_mm2: 1.28; SizeX_mm: 1.6; SizeY_mm: 0.8; SizeZ_mm: 1; AEC Category: Q200; AEC Qualified: Y; AEC Grade: 0
R37 = CMP-0025830-4: RES, 5.1 k, 5%, 0.1 W, AEC-Q200 Grade 0, 0603; Manufacturer: Vishay-Dale; Value: 5.1k; Value_Code: 5k10; Power_W: 100mW; Value2: 0.1W; VDC_V: 75V; TempCo: 200 ppm/C; SizeArea_mm2: 1.28; SizeX_mm: 1.6; SizeY_mm: 0.8; SizeZ_mm: 1; EIA_Code: E24; AEC Category: Q200; AEC Qualified: Y; AEC Grade: 0
R38 = CMP-0025753-4: RES, 20 k, 5%, 0.1 W, AEC-Q200 Grade 0, 0603; PartNumber: CRCW060320K0JNEA; Manufacturer: Vishay-Dale; Value: 20k; Value_Code: 20k0; Power_W: 100mW; Value2: 0.1W; VDC_V: 75V; TempCo: 200 ppm/C; EIA_Code: E24; U/M: EA; SizeArea_mm2: 1.28; SizeX_mm: 1.6; SizeY_mm: 0.8; SizeZ_mm: 1; AEC Category: Q200; AEC Qualified: Y; AEC Grade: 0
R39 R41-R45 = CMP-0018703-3: RES, 5.1 k, 5%, 0.25 W, AEC-Q200 Grade 0, 1206; Manufacturer: Vishay-Dale; Value: 5.1k; Value_Code: 5k10; Power_W: 250mW; Value2: 0.25W; VDC_V: 200V; TempCo: 200 ppm/C; SizeArea_mm2: 5.12; SizeX_mm: 3.2; SizeY_mm: 1.6; SizeZ_mm: 1.35; EIA_Code: E24; AEC Category: Q200; AEC Qualified: Y; AEC Grade: 0
R40 = CMP-0022601-4: RES, 7.50 k, 1%, 0.1 W, AEC-Q200 Grade 0, 0603; Manufacturer: Vishay-Dale; Power_W: 100mW; TempCo: 100 ppm/C; Value_Code: 7k50; Value: 7.50k; EIA_Code: E96; Res_ohm: 7.5k; SizeX_mm: 1.6; SizeY_mm: 0.8; SizeZ_mm: 1; Value2: 0.1W; SizeArea_mm2: 1.28; AEC Qualified: Y; VDC_V: 75V; AEC Category: Q200; AEC Grade: 0
TP16-TP23 = CMP-0078143-3: TEST POINT.  No entry in BOM.

## Sheet PR2410_Hardware.SchDoc: Hardware
size 431 x 279 mm; Date: Not shown in title block; ApprovedBy: Not shown in title block; CheckedBy: Not shown in title block; Author: Not shown in title block; CompanyName: Not shown in title block; DrawnBy: M Sunna; Engineer: Not shown in title block; Organization: Not shown in title block; Address1: Not shown in title block; Address2: Not shown in title block; Address3: Not shown in title block; Address4: Not shown in title block; DocumentNumber: 3; Revision: Use project parameter SCH_Rev; SheetNumber: 3; SheetTotal: 3; PageSetup: Record=PageOptions¦CenterHorizontal=True¦CenterVertical=True¦PrintScale=1.00¦XCorrection=1.00¦YCorrection=1.00¦PrintKind=0¦BorderSize=5000000¦LeftOffset=0¦BottomOffset=0¦Orientation=2¦PaperLength=1000¦PaperWidth=1000¦Scale=100¦PaperSource=15¦PrintQuality=600¦MediaType=1¦DitherType=10¦PaperKind=Letter¦PrintScaleMode=1
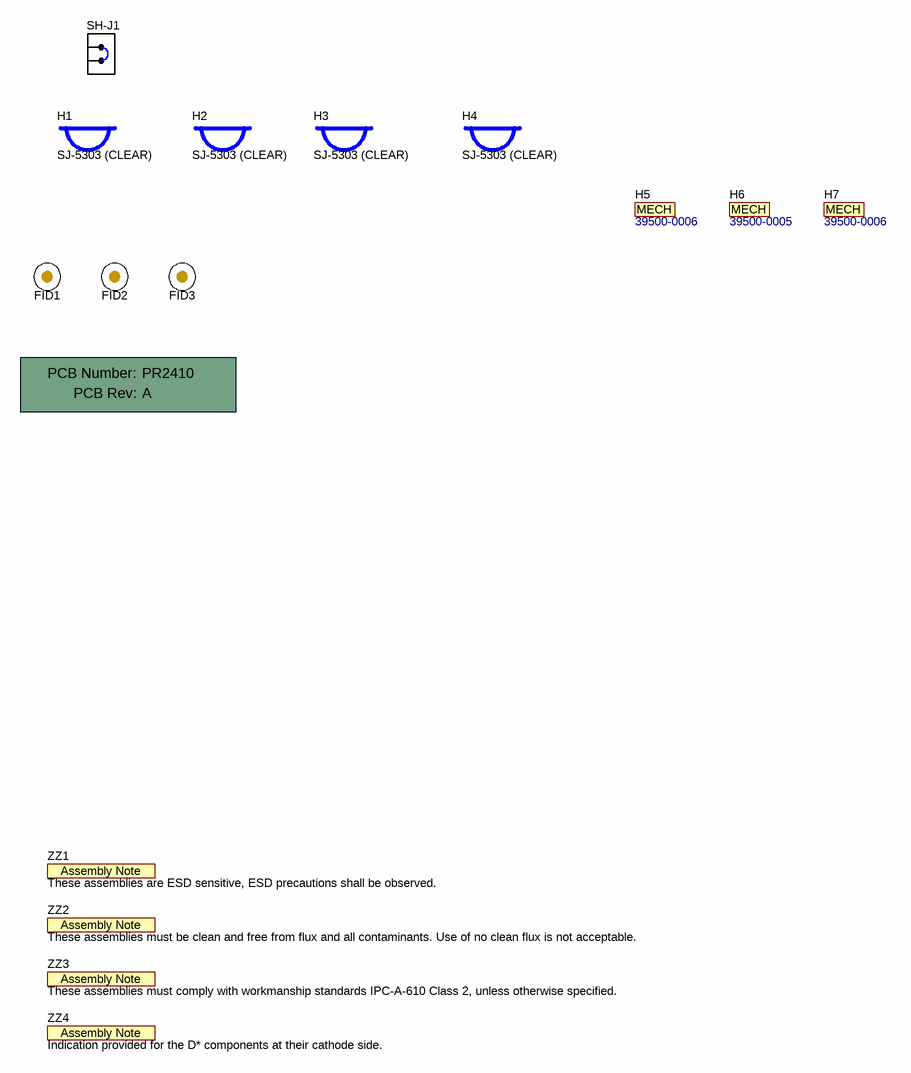
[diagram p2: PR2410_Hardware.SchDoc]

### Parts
!PCB1  Printed Circuit Board  (value not drawn)  (mechanical)
FID1  Fiducial  [Fiducial10-20]  (value not drawn)
FID2  Fiducial  [Fiducial10-20]  (value not drawn)
FID3  Fiducial  [Fiducial10-20]  (value not drawn)
H1  SJ-5303 (CLEAR)  [Bumpon_SJ5003Transparent]
H2  SJ-5303 (CLEAR)  [Bumpon_SJ5003Transparent]
H3  SJ-5303 (CLEAR)  [Bumpon_SJ5003Transparent]
H4  SJ-5303 (CLEAR)  [Bumpon_SJ5003Transparent]
H5  39500-0006  (mechanical)
H6  39500-0005  (mechanical)
H7  39500-0006  (mechanical)
SH-J1  SNT-100-BK-G  [SNT-100-BK-G]  (value not drawn)
ZZ1  These assemblies are ESD sensitive, ESD precautions shall be observed.  [AssemblyNote]  (no BOM)
ZZ2  These assemblies must be clean and free from flux and all contaminants. Use of no clean flux is not acceptable.  [AssemblyNote]  (no BOM)
ZZ3  These assemblies must comply with workmanship standards IPC-A-610 Class 2, unless otherwise specified.  [AssemblyNote]  (no BOM)
ZZ4  Indication provided for the D* components at their cathode side.  [AssemblyNote]  (no BOM)

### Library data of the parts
!PCB1 = CMP-0003618-2: Manufacturer: Any; PartNumber: PR2410
FID1-FID3 = CMP-0077181-1: Fiducial mark.  There is nothing to buy or mount.
H1-H4 = CMP-0003620-1: Bumpon, Hemisphere, 0.44 X 0.20, Clear; Manufacturer: 3M
H5-H7 = CMP-0067621-1: Terminal Block, 9 Pos, 3.5mm; Manufacturer: Molex; CompType: TERM BLOCK
SH-J1 = CMP-0003623-3: Shunt, 100mil, Gold plated, Black; Alternate PartNumber: 969102-0000-DA; Manufacturer: Samtec; Alternate Manufacturer: 3M; Value: 1x2
ZZ1 = CMP-0077236-1
ZZ2 = CMP-0077237-1
ZZ3 = CMP-0077238-1
ZZ4 = CMP-0077238-1: These assemblies must comply with workmanship standards IPC-A-610 Class 2, unless otherwise specified.

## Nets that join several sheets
PGND: PR2410_Monitor (7 pins), PR2410_FETs (6 pins)
VSS: PR2410_Monitor (22 pins), PR2410_FETs (C32.1 D9.2 Q5.2 R38.1)
16P: PR2410_Monitor (D1.2 J1.1 R2.1 TP2.1), PR2410_FETs (7 pins)
CD: PR2410_Monitor (D2.2), PR2410_FETs (10 pins)
CHG: PR2410_Monitor (U1.45), PR2410_FETs (R37.1 TP19.1)
DSG: PR2410_Monitor (U1.43), PR2410_FETs (D10.1 R41.1 TP23.1)
FUSE: PR2410_Monitor (U1.38), PR2410_FETs (R36.2)
LD: PR2410_Monitor (U1.41), PR2410_FETs (R44.2 TP22.1)
PACK: PR2410_Monitor (U1.42), PR2410_FETs (R42.2 TP21.1)

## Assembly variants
001: not fitted C25 D3 D11 FID1 FID2 FID3 TP2 TP5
